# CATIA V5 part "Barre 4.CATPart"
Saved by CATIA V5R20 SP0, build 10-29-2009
Part number: Barre 4
Bounding box of the stored display mesh (mm): x -169.738 to 244.914, y 48.153 to 211.782, z -10 to 0
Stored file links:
  C:\Users\Matthieu\Desktop\IFMA\Cours 2A\Thinkmotion\Projet_IAO_714_Matthieu_Perrusset\Barre 4.CATPart
  C:\Users\Matthieu\Desktop\IFMA\Cours 2A\Thinkmotion\Ass_skl_IAO.CATProduct
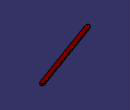
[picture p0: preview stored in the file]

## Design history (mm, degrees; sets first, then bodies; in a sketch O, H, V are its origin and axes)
AxisSystem1: origin (0, 0, 0), X (1, 0, 0), Y (0, 1, 0), Z (0, 0, 1)
Set1
  Plane1 "Plan_Ref": linked copy from another document
  Line1 "Axe_Pivot_b4b2": linked copy from another document
  Line2 "Barre_4": linked copy from another document
  Line3 "Axe_Pivot_b4b5": linked copy from another document
  Point1 "Point.E": linked copy from another document
Body1 (main body)
  Sketch1 on Plane1, origin (0, 0, 0), H (1, 0, 0), V (0, 1, 0)
    line L1 (-163.1679, 67.5404) -> (231.503, 211.1888)
    arc A1 centre (234.9232, 201.7919) radius 10 from (231.503, 211.1888) to (238.3434, 192.395) cw
    point P3 (234.9232, 201.7919)
    line L2 (238.3434, 192.395) -> (-156.3275, 48.7465)
    arc A2 centre (-159.7477, 58.1434) radius 10 from (-156.3275, 48.7465) to (-163.1679, 67.5404) cw
    point P6 (-159.7477, 58.1434)
    reference projected point E1 (-159.7477, 58.1434) from Line1
    reference projected line E2 (-159.7477, 58.1434) -> (234.9232, 201.7919) from Line2
    reference projected line E3 (-159.7477, 58.1434) -> (234.9232, 201.7919) from Line2
    reference projected point E4 (234.9232, 201.7919) from Line3
    reference projected line E5 (-159.7477, 58.1434) -> (234.9232, 201.7919) from Line2
    reference projected line E6 (-159.7477, 58.1434) -> (234.9232, 201.7919) from Line2
    distance E5 L1 = 10
    distance E6 L2 = 10
    distance P3 A1 = 10
    distance P6 A2 = 10
    coincidence: P6 E1, E4 P3
    parallelism: E2 L1, E3 L2
  Pad1: profile Sketch1, direction (0, 0, 1), length 0, opposite side length 10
